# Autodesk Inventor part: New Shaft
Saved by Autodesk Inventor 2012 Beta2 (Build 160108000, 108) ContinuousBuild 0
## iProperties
Created: 2011-01
Part Number: New Shaft
Material: Steel
Document SubType Name: Modeling
Designer: Beta-8540w
Density: 1 g/cm^3
CustomPartVersion: 1
Author: Beta-8540w
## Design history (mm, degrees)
sketch "Main Sketch"
  geometry: L1 (0, 0)-(51, 0) reference; L2 (0, 0)-(0, 5); L3 (0, 5)-(10, 5); L4 (10, 5)-(10, 6); L5 (10, 6)-(13, 6); L6 (13, 6)-(13, 12.5); L7 (25, 12.5)-(25, 6); L8 (13, 12.5)-(25, 12.5); L9 (41, 6)-(41, 5); L10 (25, 6)-(41, 6); L11 (51, 5)-(51, 0); L12 (41, 5)-(51, 5)
  constraints: 24 end point, 7 horizontal, 6 vertical
  dimensions: "d3" = 10 diameter of L3 L1 (derived); "d4" = 12 diameter of L5 L1 (derived); "d5" = 25 diameter of L8 L1 (derived); "d6" = 12 diameter of L10 L1 (derived); "d7" = 10 diameter of L12 L1 (derived)
revolve "Revolution1" sketch "Main Sketch" stored, may be unused: angle "d8" = 0 deg
chamfer "Chamfer1" distance "d9" = 0.3; stored, may be unused: second distance "d10" = 0.125, angle "d11" = 45 deg
chamfer "Chamfer2" distance "d12" = 0.3; stored, may be unused: second distance "d13" = 0.125, angle "d14" = 45 deg
node "Spur Gear Teeth1"
body "Solid1"
feature "Spur Gear Feature 1"
other parameters: "d0" = 0, "d1" = 0, "d2" = 0
